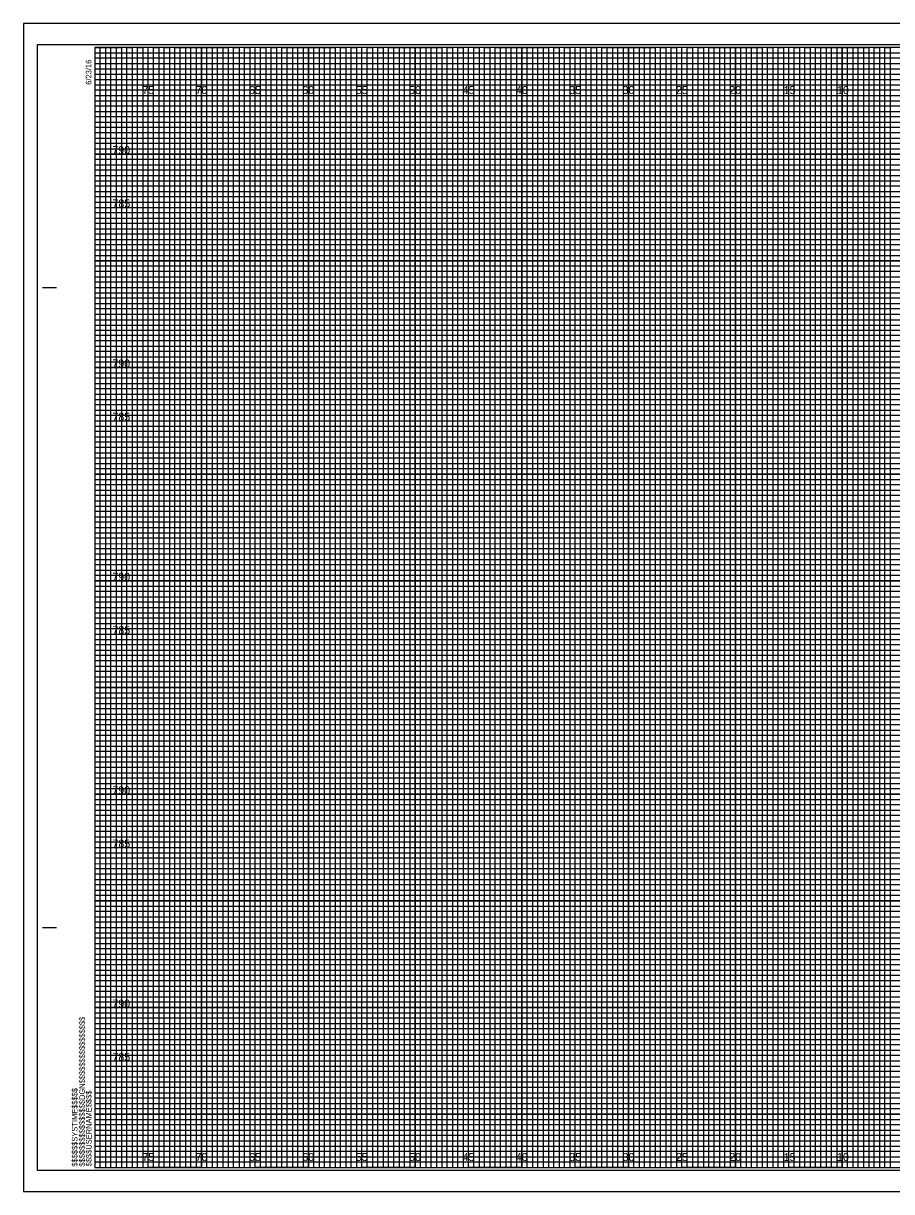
# Model space of a CAD drawing. Extents: x -7 to 162, y -2 to 107.
# Drawn here: x -6.7 to 74.6, y -2.3 to 107.3 of the extents above; entities that cross this region are included whole.
import ezdxf

# ---------------------------------------------------------------- set-up
doc = ezdxf.new("R2010")
doc.units = 0
for name, color, linetype in [('Prop XS Elevation Labels', 7, 'Continuous'), ('Prop XS Offset Labels', 7, 'Continuous'), ('Sheet Cross Section CELL', 7, 'Continuous'), ('Sheet Cross Section Grid Major CELL', 7, 'Continuous'), ('Sheet Cross Section Grid Middle CELL', 7, 'Continuous'), ('Sheet Cross Section Grid Minor 1 CELL', 7, 'Continuous'), ('Sheet Cross Section Grid Minor 2 CELL', 7, 'Continuous'), ('Sheet Cutting Line CELL', 7, 'Continuous'), ('Sheet DOT Grid CELL', 7, 'Continuous'), ('Sheet Plot Border Inside CELL', 7, 'Continuous'), ('Sheet Plot Border Outside CELL', 7, 'Continuous')]:
    doc.layers.add(name, color=color, linetype=linetype)

msp = doc.modelspace()

# ---------------------------------------------------------------- linework, layer by layer
at = {"layer": 'Sheet Cross Section CELL'}
for p, q in [((-4.9, 82.5), (-3.65, 82.5)), ((-4.85, 82.5), (-3.6, 82.5)), ((-4.9, 22.5), (-3.65, 22.5)), ((-4.85, 22.5), (-3.6, 22.5)), ((0, 0), (0, 0)), ((0, 0), (0, 0)), ((0, 0), (0, 0)), ((0, 0), (0, 0)), ((0, 0), (0, 0)), ((0, 0), (0, 0)), ((0, 0), (0, 0))]:
    msp.add_line(p, q, dxfattribs=at)
msp.add_lwpolyline([(160, 105), (0, 105), (0, 0), (160, 0)], close=True, dxfattribs=at)
at = {"layer": 'Sheet Cross Section Grid Major CELL'}
for p, q in [((5, 105), (0, 105)), ((5, 0), (5, 105)), ((15, 105), (10, 105)), ((10, 105), (10, 0)), ((15, 0), (15, 105)), ((25, 105), (20, 105)), ((20, 105), (20, 0)), ((25, 0), (25, 105)), ((35, 105), (30, 105)), ((30, 105), (30, 0)), ((35, 0), (35, 105)), ((45, 105), (40, 105)), ((40, 105), (40, 0)), ((45, 0), (45, 105)), ((55, 105), (50, 105)), ((50, 105), (50, 0)), ((55, 0), (55, 105)), ((65, 105), (60, 105)), ((60, 105), (60, 0)), ((65, 0), (65, 105)), ((75, 105), (70, 105)), ((70, 105), (70, 0)), ((10, 0), (5, 0)), ((20, 0), (15, 0)), ((30, 0), (25, 0)), ((40, 0), (35, 0)), ((50, 0), (45, 0)), ((60, 0), (55, 0)), ((70, 0), (65, 0))]:
    msp.add_line(p, q, dxfattribs=at)
for points in [[(0, 100), (160, 100), (160, 95), (0, 95)], [(0, 90), (160, 90), (160, 85), (0, 85)], [(0, 80), (160, 80), (160, 75), (0, 75)], [(0, 70), (160, 70), (160, 65), (0, 65)], [(0, 60), (160, 60), (160, 55), (0, 55)], [(0, 50), (160, 50), (160, 45), (0, 45)], [(0, 40), (160, 40), (160, 35), (0, 35)], [(0, 30), (160, 30), (160, 25), (0, 25)], [(0, 20), (160, 20), (160, 15), (0, 15)], [(0, 10), (160, 10), (160, 5), (0, 5)]]:
    msp.add_lwpolyline(points, dxfattribs=at)
at = {"layer": 'Sheet Cross Section Grid Middle CELL'}
for points in [[(0, 105), (2.5, 105), (2.5, 0), (7.5, 0), (7.5, 105), (12.5, 105), (12.5, 0), (17.5, 0), (17.5, 105), (22.5, 105), (22.5, 0), (27.5, 0), (27.5, 105), (32.5, 105), (32.5, 0), (37.5, 0), (37.5, 105), (42.5, 105), (42.5, 0), (47.5, 0), (47.5, 105), (52.5, 105), (52.5, 0), (57.5, 0), (57.5, 105), (62.5, 105), (62.5, 0), (67.5, 0), (67.5, 105), (72.5, 105), (72.5, 0), (77.5, 0)], [(0, 102.5), (137.5, 102.5)], [(0, 92.5), (160, 92.5), (160, 97.5), (0, 97.5)], [(0, 82.5), (160, 82.5), (160, 87.5), (0, 87.5)], [(0, 72.5), (160, 72.5), (160, 77.5), (0, 77.5)], [(0, 62.5), (160, 62.5), (160, 67.5), (0, 67.5)], [(0, 52.5), (160, 52.5), (160, 57.5), (0, 57.5)], [(0, 42.5), (160, 42.5), (160, 47.5), (0, 47.5)], [(0, 32.5), (160, 32.5), (160, 37.5), (0, 37.5)], [(0, 22.5), (160, 22.5), (160, 27.5), (0, 27.5)], [(0, 12.5), (160, 12.5), (160, 17.5), (0, 17.5)], [(0, 2.5), (160, 2.5), (160, 7.5), (0, 7.5)]]:
    msp.add_lwpolyline(points, dxfattribs=at)
at = {"layer": 'Sheet Cross Section Grid Minor 1 CELL'}
for p, q in [((0, 104.5), (130, 104.5)), ((130, 103.99), (0, 103.99)), ((0, 103.99), (0, 103.5)), ((0, 103.5), (130, 103.5)), ((130, 102.95), (0, 102.95)), ((0, 102.95), (0, 102)), ((0, 102), (160, 102))]:
    msp.add_line(p, q, dxfattribs=at)
for points in [[(0, 101.5), (135, 101.5), (160, 101.5), (160, 101), (0, 101)], [(0, 100.5), (160, 100.5), (160, 99.5), (0, 99.5)], [(0, 99), (160, 99), (160, 98.5), (0, 98.49)], [(0, 98), (160, 98), (160, 97), (0, 97)], [(0, 96.5), (160, 96.5), (160, 96), (0, 96)], [(0, 95.5), (160, 95.5), (160, 94.5), (0, 94.5)], [(0, 94), (160, 94), (160, 93.5), (0, 93.5)], [(0, 93), (160, 93), (160, 92), (0, 92)], [(0, 91.5), (160, 91.5), (160, 91), (0, 91)], [(0, 90.5), (160, 90.5), (160, 89.5), (0, 89.5)], [(0, 89), (160, 89), (160, 88.5), (0, 88.5)], [(0, 88), (160, 88), (160, 86.98), (160, 86.5), (160, 86), (0, 86)], [(0, 87), (160, 87), (160, 86.5), (0, 86.5)], [(0, 85.5), (160, 85.5), (160, 84.5), (0, 84.52)], [(0, 84.52), (160, 84.5), (160, 84), (0, 84)], [(0, 83.5), (160, 83.5), (160, 83), (0, 83)], [(0, 82), (160, 82), (160, 81.5), (0, 81.5)], [(0, 81), (160, 81), (160, 80.5), (0, 80.5)], [(-0.04, 79.45), (160, 79.45), (160, 78.94), (-0.04, 78.94)], [(0, 78.5), (160, 78.5), (160, 78), (0, 78)], [(0, 77), (160, 77), (160, 76.5), (0, 76.5)], [(0, 76), (160, 76), (160, 75.5), (0, 75.5)], [(0, 74.5), (160, 74.5), (160, 74), (0, 74)], [(0, 73.5), (160, 73.5), (160, 73), (0, 73)], [(0, 72), (160, 72), (160, 71.5), (0, 71.5)], [(0, 71), (160, 71), (160, 70.5), (0, 70.5)], [(0, 69.5), (160, 69.5), (160, 68.99), (0, 69)], [(0, 68.5), (160, 68.5), (160, 68), (0, 68)], [(0, 67), (160, 67), (160, 66.5), (0, 66.5)], [(0, 66), (160, 66), (160, 65.5), (0, 65.5)], [(0, 64.5), (160, 64.5), (160, 64), (0, 64)], [(0, 63.5), (160, 63.5), (160, 63), (0, 63)], [(0, 62), (160, 62), (160, 61.5), (0, 61.5)], [(0, 61), (160, 61), (160, 60.5), (0, 60.5)], [(0, 59.5), (160, 59.5), (160, 59), (0, 59)], [(0, 58.5), (160.03, 58.45), (160, 58), (0, 58)], [(0, 57), (160, 57), (160, 56.5), (0, 56.5)], [(0, 56), (160, 56), (160, 55.5), (0, 55.5)], [(0, 54.5), (160, 54.5), (160, 54), (0, 54)], [(0, 53.5), (160, 53.5), (160, 53), (0, 53)], [(0, 52), (160, 52), (160, 51.5), (0, 51.5)], [(0, 51), (160, 51), (160, 50.5), (0, 50.5)], [(0, 49.5), (160, 49.5), (160, 49), (0, 49)], [(0, 48.5), (160, 48.5), (160, 48), (0, 48)], [(0, 47), (160, 47), (160, 46.5), (0, 46.5)], [(0, 46), (160, 46), (160, 45.5), (0, 45.5)], [(0, 44.5), (160, 44.5), (160, 44), (0, 44)], [(0, 43.5), (160, 43.5), (160, 43), (0, 43)], [(0, 42), (160, 42), (160, 41.5), (0, 41.5)], [(0, 41), (160, 41), (160, 40.5), (0, 40.5)], [(0, 39.5), (160, 39.5), (160, 38.99), (0, 39)], [(0, 38.5), (160, 38.5), (160, 38), (0, 38)], [(0, 37), (160, 37), (160, 36.5), (0, 36.5)], [(0, 36), (160, 36), (160, 35.5), (0, 35.5)], [(0, 34.5), (160, 34.5), (160, 34), (0, 34)], [(0, 33.5), (160, 33.5), (160, 33), (0, 33)], [(0, 32), (160, 32), (160, 31.5), (0, 31.5)], [(0, 31), (160, 31), (160, 30.5), (0, 30.5)], [(0, 29.5), (160, 29.5), (160, 29), (0, 29)], [(0, 28.5), (160.03, 28.46), (160, 28), (0, 28)], [(0, 27), (160, 27), (160, 26.5), (0, 26.5)], [(0, 26), (160, 26), (160, 25.5), (0, 25.5)], [(0, 24.5), (160, 24.5), (160, 24), (0, 24)], [(0, 23.5), (160, 23.5), (160, 23), (0, 23)], [(0, 22), (160, 22), (160, 21.5), (0, 21.5)], [(0, 21), (160, 21), (160, 20.5), (0, 20.5)], [(0, 19.5), (160, 19.5), (160, 19), (0, 19)], [(0, 18.5), (160, 18.5), (160, 18), (0, 18)], [(0, 17), (160, 17), (160, 16.5), (0, 16.5)], [(0, 16), (160, 16), (160, 15.5), (0, 15.5)], [(0, 14.5), (160, 14.5), (160, 14), (0, 14)], [(0, 13.5), (160, 13.5), (160, 13), (0, 13)], [(0, 12), (160, 12), (160, 11.5), (0, 11.5)], [(0, 11), (160, 11), (160, 10.5), (0, 10.5)], [(0, 9.5), (160, 9.5), (160, 9), (0, 9)], [(0, 8.5), (160, 8.5), (160, 8), (0, 8)], [(0, 7), (160, 7), (160, 6.5), (0, 6.5)], [(0, 6), (160, 6), (160, 5.5), (0, 5.5)], [(0, 4.5), (160, 4.5), (160, 4), (0, 4)], [(0, 3.5), (160, 3.5), (160, 3), (0, 3)], [(0, 2), (160, 2), (160, 1.5), (0, 1.5)], [(0, 1), (160, 1), (160, 0.5), (0, 0.5)]]:
    msp.add_lwpolyline(points, dxfattribs=at)
at = {"layer": 'Sheet Cross Section Grid Minor 2 CELL'}
for points in [[(0, 0), (0.5, 0), (0.5, 105), (1, 105), (1, 0)], [(1, 0), (1.5, 0), (1.5, 105), (2, 105), (2, 0)], [(2.5, 0), (3, 0), (3, 105), (3.5, 105), (3.5, 0)], [(3.5, 0), (4, 0), (4, 105), (4.5, 105), (4.5, 0)], [(5, 0), (5.5, 0), (5.5, 105), (6, 105), (6, 0)], [(6, 0), (6.5, 0), (6.5, 105), (7, 105), (7, 0)], [(7.5, 0), (8, 0), (8, 105), (8.5, 105), (8.5, 0)], [(8.5, 0), (9, 0), (9, 105), (9.5, 105), (9.5, 0)], [(10, 0), (10.5, 0), (10.5, 105), (11, 105), (11, 0)], [(11, 0), (11.5, 0), (11.5, 105), (12, 105), (12, 0)], [(12.5, 0), (13, 0), (13, 105), (13.5, 105), (13.5, 0)], [(13.5, 0), (14, 0), (14, 105), (14.5, 105), (14.5, 0)], [(15, 0), (15.5, 0), (15.5, 105), (16, 105), (16, 0)], [(16, 0), (16.5, 0), (16.5, 105), (17, 105), (17, 0)], [(17.5, 0), (18, 0), (18, 105), (18.5, 105), (18.5, 0)], [(18.5, 0), (19, 0), (19, 105), (19.5, 105), (19.5, 0)], [(20, 0), (20.5, 0), (20.5, 105), (21, 105), (21, 0)], [(21, 0), (21.5, 0), (21.5, 105), (22, 105), (22, 0)], [(22.5, 0), (23, 0), (23, 105), (23.5, 105), (23.5, 0)], [(23.5, 0), (24, 0), (24, 105), (24.5, 105), (24.5, 0)], [(25, 0), (25.5, 0), (25.5, 105), (26, 105), (26, 0)], [(26, 0), (26.5, 0), (26.5, 105), (27, 105), (27, 0)], [(27.5, 0), (28, 0), (28, 105), (28.5, 105), (28.5, 0)], [(28.5, 0), (29, 0), (29, 105), (29.5, 105), (29.5, 0)], [(30, 0), (30.5, 0), (30.5, 105), (31, 105), (31, 0)], [(31, 0), (31.5, 0), (31.5, 105), (32, 105), (32, 0)], [(32.5, 0), (33, 0), (33, 105), (33.5, 105), (33.5, 0)], [(33.5, 0), (34, 0), (34, 105), (34.5, 105), (34.5, 0)], [(35, 0), (35.5, 0), (35.5, 105), (36, 105), (36, 0)], [(36, 0), (36.5, 0), (36.5, 105), (37, 105), (37, 0)], [(37.5, 0), (38, 0), (38, 105), (38.5, 105), (38.5, 0)], [(38.5, 0), (39, 0), (39, 105), (39.5, 105), (39.5, 0)], [(40, 0), (40.5, 0), (40.5, 105), (41, 105), (41, 0)], [(41, 0), (41.5, 0), (41.5, 105), (42, 105), (42, 0)], [(42.5, 0), (43, 0), (43, 105), (43.5, 105), (43.5, 0)], [(43.5, 0), (44, 0), (44, 105), (44.5, 105), (44.5, 0)], [(45, 0), (45.5, 0), (45.5, 105), (46, 105), (46, 0)], [(46, 0), (46.5, 0), (46.5, 105), (47, 105), (47, 0)], [(47.5, 0), (48, 0), (48, 105), (48.5, 105), (48.5, 0)], [(48.5, 0), (49, 0), (49, 105), (49.5, 105), (49.5, 0)], [(50, 0), (50.5, 0), (50.5, 105), (51, 105), (51, 0)], [(51, 0), (51.5, 0), (51.5, 105), (52, 105), (52, 0)], [(52.5, 0), (53, 0), (53, 105), (53.5, 105), (53.5, 0)], [(53.5, 0), (54, 0), (54, 105), (54.5, 105), (54.5, 0)], [(55, 0), (55.5, 0), (55.5, 105), (56, 105), (56, 0)], [(56, 0), (56.5, 0), (56.5, 105), (57, 105), (57, 0)], [(57.5, 0), (58, 0), (58, 105), (58.5, 105), (58.5, 0)], [(58.5, 0), (59, 0), (59, 105), (59.5, 105), (59.5, 0)], [(60, 0), (60.5, 0), (60.5, 105), (61, 105), (61, 0)], [(61, 0), (61.5, 0), (61.5, 105), (62, 105), (62, 0)], [(62.5, 0), (63, 0), (63, 105), (63.5, 105), (63.5, 0)], [(63.5, 0), (64, 0), (64, 105), (64.5, 105), (64.5, 0)], [(65, 0), (65.5, 0), (65.5, 105), (66, 105), (66, 0)], [(66, 0), (66.5, 0), (66.5, 105), (67, 105), (67, 0)], [(67.5, 0), (68, 0), (68, 105), (68.5, 105), (68.5, 0)], [(68.5, 0), (69, 0), (69, 105), (69.5, 105), (69.5, 0)], [(70, 0), (70.5, 0), (70.5, 105), (71, 105), (71, 0)], [(71, 0), (71.5, 0), (71.5, 105), (72, 105), (72, 0)], [(72.5, 0), (73, 0), (73, 105), (73.5, 105), (73.5, 0)], [(73.5, 0), (74, 0), (74, 105), (74.5, 105), (74.5, 0)]]:
    msp.add_lwpolyline(points, dxfattribs=at)
at = {"layer": 'Sheet Cutting Line CELL'}
for p, q in [((161.65, 107.25), (-6.7, 107.25)), ((-6.7, 107.25), (-6.7, -2.25)), ((-6.7, -2.25), (161.65, -2.25))]:
    msp.add_line(p, q, dxfattribs=at)
at = {"layer": 'Sheet DOT Grid CELL'}
for p, q in [((5, 0), (5, 105)), ((10, 0), (10, 105)), ((15, 0), (15, 105)), ((20, 0), (20, 105)), ((25, 0), (25, 105)), ((30, 0), (30, 105)), ((35, 0), (35, 105)), ((40, 0), (40, 105)), ((45, 0), (45, 105)), ((50, 0), (50, 105)), ((55, 0), (55, 105)), ((60, 0), (60, 105)), ((65, 0), (65, 105)), ((70, 0), (70, 105)), ((0, 100), (160, 100)), ((0, 95), (160, 95)), ((0, 90), (160, 90)), ((0, 85), (160, 85)), ((0, 80), (160, 80)), ((0, 75), (160, 75)), ((0, 70), (160, 70)), ((0, 65), (160, 65)), ((0, 60), (160, 60)), ((0, 55), (160, 55)), ((0, 50), (160, 50)), ((0, 45), (160, 45)), ((0, 40), (160, 40)), ((0, 35), (160, 35)), ((0, 30), (160, 30)), ((0, 25), (160, 25)), ((0, 20), (160, 20)), ((0, 15), (160, 15)), ((0, 10), (160, 10)), ((0, 5), (160, 5))]:
    msp.add_line(p, q, dxfattribs=at)
at = {"layer": 'Sheet Plot Border Inside CELL'}
msp.add_lwpolyline([(-5.4, -0.25), (161.2, -0.25), (161.2, 105.25), (-5.4, 105.25)], close=True, dxfattribs=at)
at = {"layer": 'Sheet Plot Border Outside CELL'}
msp.add_lwpolyline([(-6.7, -2.25), (161.65, -2.25), (161.65, 107.25), (-6.7, 107.25)], close=True, dxfattribs=at)

# ---------------------------------------------------------------- texts
at = {"layer": 'Prop XS Elevation Labels'}
for s, p in [('790', (1.63, 95)), ('785', (1.64, 90)), ('790', (1.63, 75)), ('785', (1.64, 70)), ('790', (1.63, 55)), ('785', (1.64, 50)), ('790', (1.63, 35)), ('785', (1.64, 30)), ('790', (1.63, 15)), ('785', (1.64, 10))]:
    msp.add_text(s, height=0.75, dxfattribs=at).set_placement(p)
at = {"layer": 'Prop XS Offset Labels'}
for s, p in [('75', (4.44, 100.62)), ('70', (9.43, 100.62)), ('65', (14.44, 100.62)), ('60', (19.43, 100.62)), ('55', (24.44, 100.62)), ('50', (29.43, 100.62)), ('45', (34.44, 100.62)), ('40', (39.43, 100.62)), ('35', (44.44, 100.62)), ('30', (49.43, 100.62)), ('25', (54.44, 100.62)), ('20', (59.43, 100.62)), ('15', (64.53, 100.62)), ('10', (69.52, 100.62)), ('75', (4.44, 0.62)), ('70', (9.43, 0.62)), ('65', (14.44, 0.62)), ('60', (19.43, 0.62)), ('55', (24.44, 0.62)), ('50', (29.43, 0.62)), ('45', (34.44, 0.62)), ('40', (39.43, 0.62)), ('35', (44.44, 0.62)), ('30', (49.43, 0.62)), ('25', (54.44, 0.62)), ('20', (59.43, 0.62)), ('15', (64.53, 0.62)), ('10', (69.52, 0.62))]:
    msp.add_text(s, height=0.75, dxfattribs=at).set_placement(p)
at = {"layer": 'Sheet Cross Section CELL'}
for s, p in [('6/23/16', (-0.33, 101.5)), ('$$$$$$$$$$$$$$$$DGN$$$$$$$$$$$$$$$$', (-0.94, 0.09)), ('$$$$$$SYSTIME$$$$$', (-1.63, 0.09)), ('$$$$USERNAME$$$$', (-0.31, 0.12))]:
    msp.add_text(s, height=0.525, rotation=90, dxfattribs=at).set_placement(p)

doc.saveas('drawing.dxf')
